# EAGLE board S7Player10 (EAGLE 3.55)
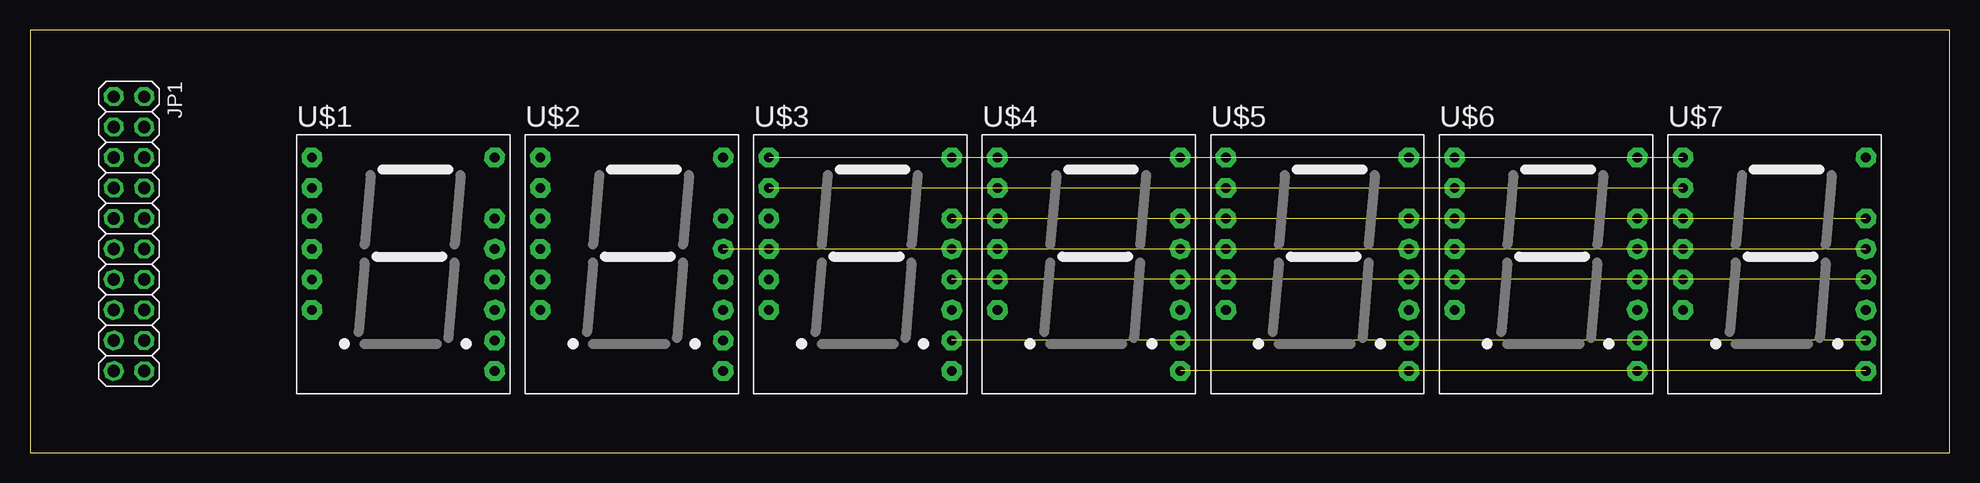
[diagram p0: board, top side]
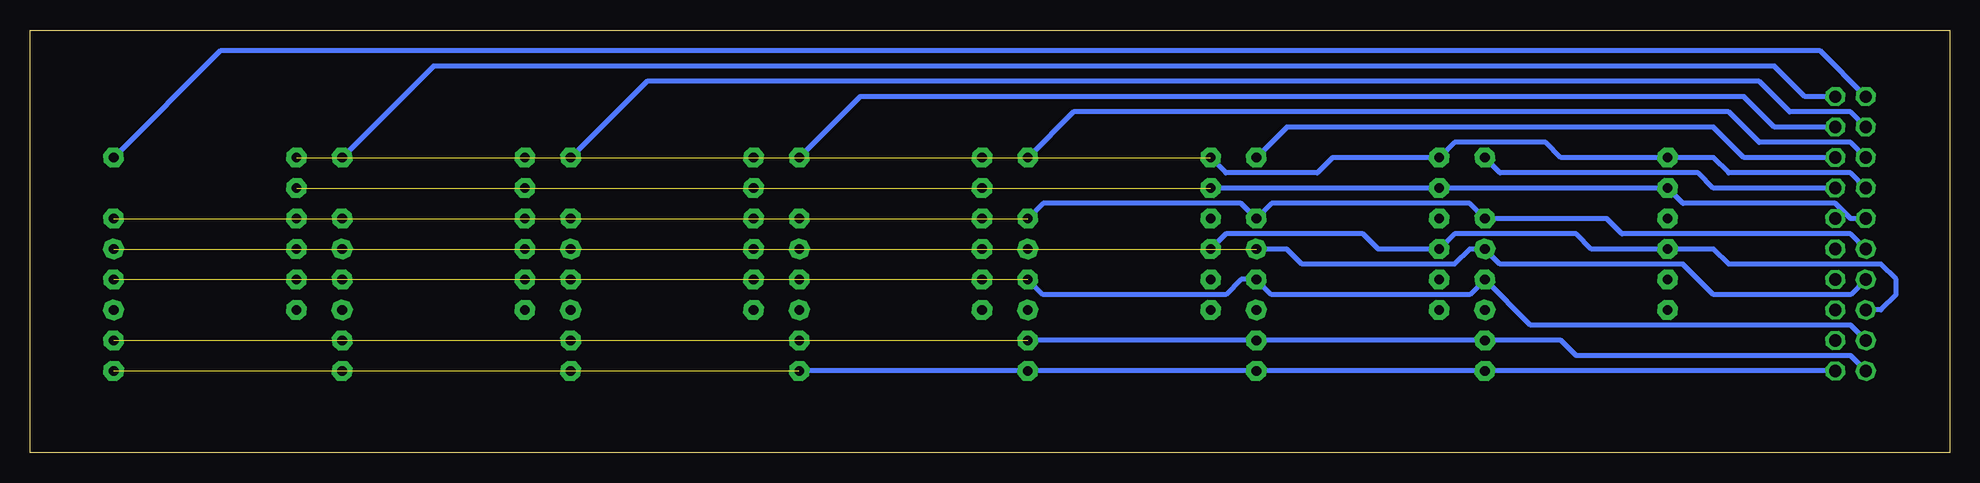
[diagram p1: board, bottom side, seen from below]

Size 160 x 35.23 mm. Coordinates in mm from the lower left corner, seen from the top.
Outline: 0,0 160,0 160,35.23 0,35.23 0,0
Copper layers used: Bottom

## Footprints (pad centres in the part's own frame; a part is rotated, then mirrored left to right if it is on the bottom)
10 = drill 1.016 pad 1.6 octagon:  -11.43,-1.27;  -11.43,1.27;  -8.89,-1.27;  -8.89,1.27;  -6.35,-1.27;  -6.35,1.27;  -3.81,-1.27;  -3.81,1.27;  -1.27,-1.27;  -1.27,1.27;  1.27,-1.27;  1.27,1.27;  3.81,-1.27;  3.81,1.27;  6.35,-1.27;  6.35,1.27;  8.89,-1.27;  8.89,1.27;  11.43,-1.27;  11.43,1.27
08-11 = drill 0.813 pad 1.676 octagon:  -7.62,15.24;  -7.62,12.7;  -7.62,10.16;  7.62,15.24;  7.62,12.7;  7.62,10.16;  7.62,5.08;  7.62,7.62;  -7.62,17.78;  -7.62,20.32;  -7.62,22.86;  7.62,17.78;  7.62,22.86

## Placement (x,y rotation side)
JP1  PINHD-2X10  [10]  8.25,18.25 270 top
U$1  SC08-11  [08-11]  31.11,1.74 0 top
U$2  SC08-11  [08-11]  50.16,1.74 0 top
U$3  SC08-11  [08-11]  69.21,1.74 0 top
U$4  SC08-11  [08-11]  88.26,1.74 0 top
U$5  SC08-11  [08-11]  107.31,1.74 0 top
U$6  SC08-11  [08-11]  126.36,1.74 0 top
U$7  SC08-11  [08-11]  145.41,1.74 0 top

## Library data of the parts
JP1 = PINHEAD
U$1-U$7 = SPECIAL

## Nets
A: JP1. U$1. U$2. U$3. U$4. U$5. U$6. U$7.
B: JP1. U$1. U$2. U$3. U$4. U$5. U$6. U$7.
C: JP1. U$1. U$2. U$3. U$4. U$5. U$6. U$7.
D: JP1. U$1. U$2. U$3. U$4. U$5. U$6. U$7.
DOT: JP1. U$1. U$2. U$3. U$4. U$5. U$6. U$7.
E: JP1. U$1. U$2. U$3. U$4. U$5. U$6. U$7.
F: JP1. U$1. U$2. U$3. U$4. U$5. U$6. U$7.
G: JP1. U$1. U$2. U$3. U$4. U$5. U$6. U$7.
STR1: JP1. U$1.
STR2: JP1. U$2.
STR3: JP1. U$3.
STR4: JP1. U$4.
STR5: JP1. U$5.
STR6: JP1. U$6.
STR7: JP1. U$7.

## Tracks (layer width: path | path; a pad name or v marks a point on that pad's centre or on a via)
A  (4 unrouted)
  Bottom 0.406: 6.98,22.06 8.25,23.33 18.41,23.33 19.68,24.6 23.49,24.6 32.38,24.6 33.65,25.87 41.27,25.87 42.54,24.6 51.43,24.6 52.7,23.33 60.32,23.33 61.59,24.6
B  (4 unrouted)
  Bottom 0.406: 6.98,16.98 8.25,18.25 27.3,18.25 28.57,19.52 38.73,19.52 40,20.79 56.51,20.79 57.78,19.52 59.05,20.79 75.56,20.79 76.83,19.52
C  (4 unrouted)
  Bottom 0.406: 6.98,9.36 8.25,10.63 34.92,10.63 38.73,14.44 40,13.17 56.51,13.17 57.78,14.44 59.05,14.44 60.32,13.17 75.56,13.17 76.83,14.44
D  (4 unrouted)
  Bottom 0.406: 6.98,6.82 8.25,8.09 31.11,8.09 32.38,9.36 38.73,9.36 57.78,9.36 76.83,9.36
DOT  (3 unrouted)
  Bottom 0.406: JP1. 38.73,6.82 57.78,6.82 76.83,6.82 95.88,6.82
E  (4 unrouted)
  Bottom 0.406: 6.98,11.9 5.71,11.9 4.44,13.17 4.44,14.44 5.71,15.71 18.41,15.71 19.68,16.98 23.49,16.98 29.84,16.98 31.11,18.25 41.27,18.25 42.54,16.98 47.62,16.98 48.89,18.25 60.32,18.25 61.59,16.98
F  (4 unrouted)
  Bottom 0.406: 6.98,19.52 8.25,19.52 9.52,20.79 22.22,20.79 23.49,22.06 42.54,22.06 61.59,22.06
G  (5 unrouted)
  Bottom 0.406: 6.98,14.44 8.25,13.17 19.68,13.17 22.22,15.71 37.46,15.71 38.73,16.98 40,16.98 41.27,15.71 53.97,15.71 55.24,16.98 57.78,16.98
STR1
  Bottom 0.406: 9.52,22.06 19.68,22.06 20.95,23.33 37.46,23.33 U$1.
STR2
  Bottom 0.406: 9.52,24.6 17.14,24.6 19.68,27.14 55.24,27.14 U$2.
STR3
  Bottom 0.406: 6.98,24.6 8.25,25.87 15.87,25.87 18.41,28.41 73.02,28.41 U$3.
STR4
  Bottom 0.406: 9.52,27.14 14.6,27.14 17.14,29.68 90.8,29.68 U$4.
STR5
  Bottom 0.406: 6.98,27.14 8.25,28.41 13.33,28.41 15.87,30.95 108.58,30.95 U$5.
STR6
  Bottom 0.406: 9.52,29.68 12.06,29.68 14.6,32.22 126.36,32.22 U$6.
STR7
  Bottom 0.406: 6.98,29.68 10.79,33.49 144.14,33.49 U$7.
